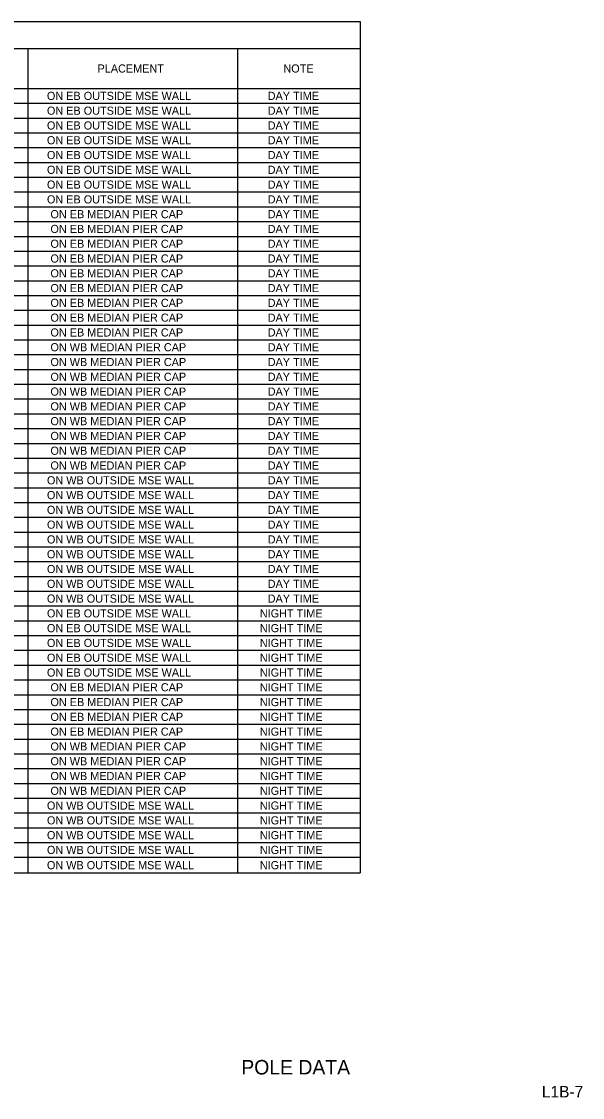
# Model space of a CAD drawing. Extents: x -816.7 to -800.9, y -2209.6 to -2187.8.
# Drawn here: x -805.77 to -800.94, y -2209.39 to -2200.11 of the extents above; entities that cross this region are included whole.
import ezdxf

# ---------------------------------------------------------------- set-up
doc = ezdxf.new("R2010")
doc.units = 0
for name, color, linetype in [('PlotBorder_dp', 7, 'Continuous'), ('SheetBorder_dp', 7, 'Continuous'), ('SheetLines_dp', 7, 'Continuous'), ('TextMinor', 7, 'Continuous'), ('TextMisc', 7, 'Continuous'), ('TextShtNo', 7, 'Continuous')]:
    doc.layers.add(name, color=color, linetype=linetype)

msp = doc.modelspace()

# ---------------------------------------------------------------- linework, layer by layer
at = {"layer": 'PlotBorder_dp'}
for p, q in [((-805.7186, -2200.3435), (-805.7186, -2207.4535)), ((-805.7186, -2200.3435), (-805.7186, -2207.4535)), ((-803.9111, -2200.3435), (-803.9111, -2207.4535)), ((-813.1586, -2200.6885), (-802.8536, -2200.6885)), ((-803.9111, -2207.3185), (-803.9111, -2207.4535))]:
    msp.add_line(p, q, dxfattribs=at)
at = {"layer": 'SheetLines_dp'}
for p, q in [((-813.1586, -2200.111), (-802.8536, -2200.111)), ((-802.8536, -2200.111), (-802.8536, -2207.4535)), ((-813.1586, -2200.3435), (-802.8536, -2200.3435)), ((-813.1586, -2200.3435), (-802.8536, -2200.3435)), ((-813.1586, -2207.4535), (-802.8536, -2207.4535))]:
    msp.add_line(p, q, dxfattribs=at)
at = {"layer": 'TextMinor'}
for p, q in [((-813.1586, -2200.6885), (-802.8536, -2200.6885)), ((-813.1586, -2200.816), (-802.8536, -2200.816)), ((-813.1586, -2200.816), (-802.8536, -2200.816)), ((-813.1586, -2200.9435), (-802.8536, -2200.9435)), ((-813.1586, -2200.9435), (-802.8536, -2200.9435)), ((-813.1586, -2201.071), (-802.8536, -2201.071)), ((-813.1586, -2201.071), (-802.8536, -2201.071)), ((-813.1586, -2201.1985), (-802.8536, -2201.1985)), ((-813.1586, -2201.1985), (-802.8536, -2201.1985)), ((-813.1586, -2201.326), (-802.8536, -2201.326)), ((-813.1586, -2201.326), (-802.8536, -2201.326)), ((-813.1586, -2201.4535), (-802.8536, -2201.4535)), ((-810.2111, -2201.4535), (-802.8536, -2201.4535)), ((-813.1586, -2201.581), (-802.8536, -2201.581)), ((-813.1586, -2201.581), (-802.8536, -2201.581)), ((-813.1586, -2201.7085), (-802.8536, -2201.7085)), ((-813.1586, -2201.7085), (-802.8536, -2201.7085)), ((-813.1586, -2201.836), (-802.8536, -2201.836)), ((-813.1586, -2201.836), (-802.8536, -2201.836)), ((-813.1586, -2201.9635), (-802.8536, -2201.9635)), ((-813.1586, -2201.9635), (-802.8536, -2201.9635)), ((-813.1586, -2202.091), (-802.8536, -2202.091)), ((-813.1586, -2202.091), (-802.8536, -2202.091)), ((-813.1586, -2202.2185), (-802.8536, -2202.2185)), ((-813.1586, -2202.2185), (-802.8536, -2202.2185)), ((-813.1586, -2202.346), (-802.8536, -2202.346)), ((-813.1586, -2202.346), (-802.8536, -2202.346)), ((-813.1586, -2202.4735), (-802.8536, -2202.4735)), ((-813.1586, -2202.4735), (-802.8536, -2202.4735)), ((-813.1586, -2202.601), (-802.8536, -2202.601)), ((-813.1586, -2202.601), (-802.8536, -2202.601)), ((-813.1586, -2202.7285), (-802.8536, -2202.7285)), ((-813.1586, -2202.7285), (-802.8536, -2202.7285)), ((-813.1586, -2202.856), (-802.8536, -2202.856)), ((-813.1586, -2202.856), (-802.8536, -2202.856)), ((-813.1586, -2202.9835), (-802.8536, -2202.9835)), ((-813.1586, -2202.9835), (-802.8536, -2202.9835)), ((-813.1586, -2203.111), (-802.8536, -2203.111)), ((-813.1586, -2203.111), (-802.8536, -2203.111)), ((-813.1586, -2203.2385), (-802.8536, -2203.2385)), ((-813.1586, -2203.2385), (-802.8536, -2203.2385)), ((-813.1586, -2203.366), (-802.8536, -2203.366)), ((-813.1586, -2203.366), (-802.8536, -2203.366)), ((-813.1586, -2203.4935), (-802.8536, -2203.4935)), ((-813.1586, -2203.4935), (-802.8536, -2203.4935)), ((-813.1586, -2203.621), (-802.8536, -2203.621)), ((-813.1586, -2203.621), (-802.8536, -2203.621)), ((-813.1586, -2203.7485), (-802.8536, -2203.7485)), ((-813.1586, -2203.7485), (-802.8536, -2203.7485)), ((-813.1586, -2203.876), (-802.8536, -2203.876)), ((-813.1586, -2203.876), (-802.8536, -2203.876)), ((-813.1586, -2204.0035), (-802.8536, -2204.0035)), ((-813.1586, -2204.0035), (-802.8536, -2204.0035)), ((-813.1586, -2204.131), (-802.8536, -2204.131)), ((-813.1586, -2204.131), (-802.8536, -2204.131)), ((-813.1586, -2204.2585), (-802.8536, -2204.2585)), ((-813.1586, -2204.2585), (-802.8536, -2204.2585)), ((-813.1586, -2204.386), (-802.8536, -2204.386)), ((-813.1586, -2204.386), (-802.8536, -2204.386)), ((-813.1586, -2204.5135), (-802.8536, -2204.5135)), ((-813.1586, -2204.5135), (-802.8536, -2204.5135)), ((-813.1586, -2204.641), (-802.8536, -2204.641)), ((-813.1586, -2204.641), (-802.8536, -2204.641)), ((-813.1586, -2204.7685), (-802.8536, -2204.7685)), ((-813.1586, -2204.7685), (-802.8536, -2204.7685)), ((-813.1586, -2204.896), (-802.8536, -2204.896)), ((-813.1586, -2204.896), (-802.8536, -2204.896)), ((-813.1586, -2205.0235), (-802.8536, -2205.0235)), ((-813.1586, -2205.0235), (-802.8536, -2205.0235)), ((-813.1586, -2205.151), (-802.8536, -2205.151)), ((-805.7186, -2205.151), (-802.8536, -2205.151)), ((-813.1586, -2205.2785), (-802.8536, -2205.2785)), ((-813.1586, -2205.2785), (-802.8536, -2205.2785)), ((-813.1586, -2205.406), (-802.8536, -2205.406)), ((-813.1586, -2205.406), (-802.8536, -2205.406)), ((-813.1586, -2205.5335), (-802.8536, -2205.5335)), ((-813.1586, -2205.5335), (-802.8536, -2205.5335)), ((-813.1586, -2205.661), (-802.8536, -2205.661)), ((-813.1586, -2205.661), (-802.8536, -2205.661)), ((-813.1586, -2205.7885), (-802.8536, -2205.7885)), ((-813.1586, -2205.7885), (-802.8536, -2205.7885)), ((-813.1586, -2205.916), (-802.8536, -2205.916)), ((-810.2111, -2205.916), (-802.8536, -2205.916)), ((-813.1586, -2206.0435), (-802.8536, -2206.0435)), ((-813.1586, -2206.0435), (-802.8536, -2206.0435)), ((-813.1586, -2206.171), (-802.8536, -2206.171)), ((-813.1586, -2206.171), (-802.8536, -2206.171)), ((-813.1586, -2206.2985), (-802.8536, -2206.2985)), ((-813.1586, -2206.2985), (-802.8536, -2206.2985)), ((-813.1586, -2206.426), (-802.8536, -2206.426)), ((-813.1586, -2206.426), (-802.8536, -2206.426)), ((-813.1586, -2206.5535), (-802.8536, -2206.5535)), ((-813.1586, -2206.5535), (-802.8536, -2206.5535)), ((-813.1586, -2206.681), (-802.8536, -2206.681)), ((-813.1586, -2206.681), (-802.8536, -2206.681)), ((-813.1586, -2206.8085), (-802.8536, -2206.8085)), ((-813.1586, -2206.8085), (-802.8536, -2206.8085)), ((-813.1586, -2206.936), (-802.8536, -2206.936)), ((-813.1586, -2206.936), (-802.8536, -2206.936)), ((-813.1586, -2207.0635), (-802.8536, -2207.0635)), ((-813.1586, -2207.0635), (-802.8536, -2207.0635)), ((-813.1586, -2207.191), (-802.8536, -2207.191)), ((-813.1586, -2207.191), (-802.8536, -2207.191)), ((-813.1586, -2207.3185), (-802.8536, -2207.3185)), ((-813.1586, -2207.3185), (-802.8536, -2207.3185))]:
    msp.add_line(p, q, dxfattribs=at)

# ---------------------------------------------------------------- texts
at = {"layer": 'SheetBorder_dp'}
for s, p in [('PLACEMENT', (-805.118, -2200.551)), ('NOTE', (-803.5156, -2200.551)), ('ON EB OUTSIDE MSE WALL', (-805.5544, -2200.7872)), ('DAY TIME', (-803.6511, -2200.7872)), ('ON EB OUTSIDE MSE WALL', (-805.5544, -2200.9147)), ('DAY TIME', (-803.6511, -2200.9147)), ('ON EB OUTSIDE MSE WALL', (-805.5544, -2201.0422)), ('DAY TIME', (-803.6511, -2201.0422)), ('ON EB OUTSIDE MSE WALL', (-805.5544, -2201.1697)), ('DAY TIME', (-803.6511, -2201.1697)), ('ON EB OUTSIDE MSE WALL', (-805.5544, -2201.2972)), ('DAY TIME', (-803.6511, -2201.2972)), ('ON EB OUTSIDE MSE WALL', (-805.5544, -2201.4247)), ('DAY TIME', (-803.6511, -2201.4247)), ('ON EB OUTSIDE MSE WALL', (-805.5544, -2201.5522)), ('DAY TIME', (-803.6511, -2201.5522)), ('ON EB OUTSIDE MSE WALL', (-805.5544, -2201.6797)), ('DAY TIME', (-803.6511, -2201.6797)), ('ON EB MEDIAN PIER CAP', (-805.5241, -2201.8072)), ('DAY TIME', (-803.6511, -2201.8072)), ('ON EB MEDIAN PIER CAP', (-805.5241, -2201.9347)), ('DAY TIME', (-803.6511, -2201.9347)), ('ON EB MEDIAN PIER CAP', (-805.5241, -2202.0622)), ('DAY TIME', (-803.6511, -2202.0622)), ('ON EB MEDIAN PIER CAP', (-805.5241, -2202.1897)), ('DAY TIME', (-803.6511, -2202.1897)), ('ON EB MEDIAN PIER CAP', (-805.5241, -2202.3172)), ('DAY TIME', (-803.6511, -2202.3172)), ('ON EB MEDIAN PIER CAP', (-805.5241, -2202.4447)), ('DAY TIME', (-803.6511, -2202.4447)), ('ON EB MEDIAN PIER CAP', (-805.5241, -2202.5722)), ('DAY TIME', (-803.6511, -2202.5722)), ('ON EB MEDIAN PIER CAP', (-805.5241, -2202.6997)), ('DAY TIME', (-803.6511, -2202.6997)), ('ON EB MEDIAN PIER CAP', (-805.5241, -2202.8272)), ('DAY TIME', (-803.6511, -2202.8272)), ('ON WB MEDIAN PIER CAP', (-805.5241, -2202.9547)), ('DAY TIME', (-803.6511, -2202.9547)), ('ON WB MEDIAN PIER CAP', (-805.5241, -2203.0822)), ('DAY TIME', (-803.6511, -2203.0822)), ('ON WB MEDIAN PIER CAP', (-805.5241, -2203.2097)), ('DAY TIME', (-803.6511, -2203.2097)), ('ON WB MEDIAN PIER CAP', (-805.5241, -2203.3372)), ('DAY TIME', (-803.6511, -2203.3372)), ('ON WB MEDIAN PIER CAP', (-805.5241, -2203.4647)), ('DAY TIME', (-803.6511, -2203.4647)), ('ON WB MEDIAN PIER CAP', (-805.5241, -2203.5922)), ('DAY TIME', (-803.6511, -2203.5922)), ('ON WB MEDIAN PIER CAP', (-805.5241, -2203.7197)), ('DAY TIME', (-803.6511, -2203.7197)), ('ON WB MEDIAN PIER CAP', (-805.5241, -2203.8472)), ('DAY TIME', (-803.6511, -2203.8472)), ('ON WB MEDIAN PIER CAP', (-805.5241, -2203.9747)), ('DAY TIME', (-803.6511, -2203.9747)), ('ON WB OUTSIDE MSE WALL', (-805.5544, -2204.1022)), ('DAY TIME', (-803.6511, -2204.1022)), ('ON WB OUTSIDE MSE WALL', (-805.5544, -2204.2297)), ('DAY TIME', (-803.6511, -2204.2297)), ('ON WB OUTSIDE MSE WALL', (-805.5544, -2204.3572)), ('DAY TIME', (-803.6511, -2204.3572)), ('ON WB OUTSIDE MSE WALL', (-805.5544, -2204.4847)), ('DAY TIME', (-803.6511, -2204.4847)), ('ON WB OUTSIDE MSE WALL', (-805.5544, -2204.6122)), ('DAY TIME', (-803.6511, -2204.6122)), ('ON WB OUTSIDE MSE WALL', (-805.5544, -2204.7397)), ('DAY TIME', (-803.6511, -2204.7397)), ('ON WB OUTSIDE MSE WALL', (-805.5544, -2204.8672)), ('DAY TIME', (-803.6511, -2204.8672)), ('ON WB OUTSIDE MSE WALL', (-805.5544, -2204.9947)), ('DAY TIME', (-803.6511, -2204.9947)), ('ON WB OUTSIDE MSE WALL', (-805.5544, -2205.1222)), ('DAY TIME', (-803.6511, -2205.1222)), ('ON EB OUTSIDE MSE WALL', (-805.5544, -2205.2497)), ('NIGHT TIME', (-803.7189, -2205.2497)), ('ON EB OUTSIDE MSE WALL', (-805.5544, -2205.3772)), ('NIGHT TIME', (-803.7189, -2205.3772)), ('ON EB OUTSIDE MSE WALL', (-805.5544, -2205.5047)), ('NIGHT TIME', (-803.7189, -2205.5047)), ('ON EB OUTSIDE MSE WALL', (-805.5544, -2205.6322)), ('NIGHT TIME', (-803.7189, -2205.6322)), ('ON EB OUTSIDE MSE WALL', (-805.5544, -2205.7597)), ('NIGHT TIME', (-803.7189, -2205.7597)), ('ON EB MEDIAN PIER CAP', (-805.5241, -2205.8872)), ('NIGHT TIME', (-803.7189, -2205.8872)), ('ON EB MEDIAN PIER CAP', (-805.5241, -2206.0147)), ('NIGHT TIME', (-803.7189, -2206.0147)), ('ON EB MEDIAN PIER CAP', (-805.5241, -2206.1422)), ('NIGHT TIME', (-803.7189, -2206.1422)), ('ON EB MEDIAN PIER CAP', (-805.5241, -2206.2697)), ('NIGHT TIME', (-803.7189, -2206.2697)), ('ON WB MEDIAN PIER CAP', (-805.5241, -2206.3972)), ('NIGHT TIME', (-803.7189, -2206.3972)), ('ON WB MEDIAN PIER CAP', (-805.5241, -2206.5247)), ('NIGHT TIME', (-803.7189, -2206.5247)), ('ON WB MEDIAN PIER CAP', (-805.5241, -2206.6522)), ('NIGHT TIME', (-803.7189, -2206.6522)), ('ON WB MEDIAN PIER CAP', (-805.5241, -2206.7797)), ('NIGHT TIME', (-803.7189, -2206.7797)), ('ON WB OUTSIDE MSE WALL', (-805.5544, -2206.9072)), ('NIGHT TIME', (-803.7189, -2206.9072)), ('ON WB OUTSIDE MSE WALL', (-805.5544, -2207.0347)), ('NIGHT TIME', (-803.7189, -2207.0347)), ('ON WB OUTSIDE MSE WALL', (-805.5544, -2207.1622)), ('NIGHT TIME', (-803.7189, -2207.1622)), ('ON WB OUTSIDE MSE WALL', (-805.5544, -2207.2897)), ('NIGHT TIME', (-803.7189, -2207.2897)), ('ON WB OUTSIDE MSE WALL', (-805.5544, -2207.421)), ('NIGHT TIME', (-803.7189, -2207.421))]:
    msp.add_text(s, height=0.07, dxfattribs=at).set_placement(p)
at = {"layer": 'TextMisc'}
msp.add_text('POLE DATA', height=0.125, dxfattribs=at).set_placement((-803.8787, -2209.1911))
at = {"layer": 'TextShtNo'}
msp.add_text('L1B-7  ', height=0.1, dxfattribs=at).set_placement((-801.2872, -2209.3895))

doc.saveas('drawing.dxf')
